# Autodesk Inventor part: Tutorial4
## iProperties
Created: 2009-04
Part Number: Tutorial4
Document SubType Name: Modeling
Designer: Sham
Density: 1 g/cm^3
Author: Sham
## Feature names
1. Revolution1
